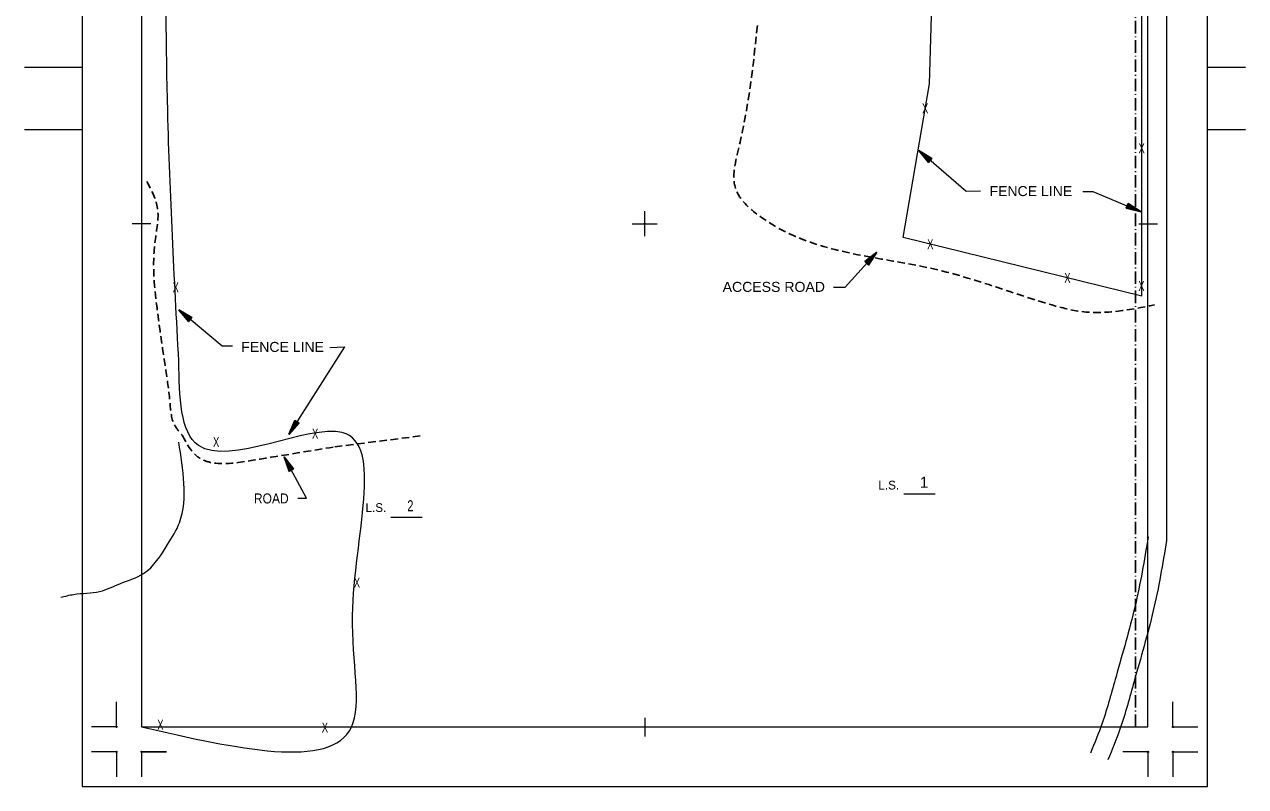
# Model space of a CAD drawing. Extents: x -496 to 480, y -450 to 700.
# Drawn here: x -496 to 480, y -450 to 159 of the extents above; entities that cross this region are included whole.
import ezdxf
from ezdxf.enums import TextEntityAlignment as Align

# ---------------------------------------------------------------- set-up
doc = ezdxf.new("R2010")
doc.units = 0
doc.header["$LTSCALE"] = 2
doc.header["$PDMODE"] = 32
doc.header["$PDSIZE"] = 1
doc.linetypes.add('DOT_DASHED', pattern=[7.7, 5, -1.2, 0.3, -1.2])
doc.linetypes.add('MEDIUM_DASHED', pattern=[4.5, 3, -1.5])
for name, color, linetype, lineweight in [('1', 7, 'Continuous', 13), ('3', 7, 'Continuous', 13), ('4', 7, 'Continuous', 25)]:
    doc.layers.add(name, color=color, linetype=linetype, lineweight=lineweight)

msp = doc.modelspace()

# ---------------------------------------------------------------- linework, layer by layer
at = {"layer": '1'}
for p, q in [((-402.391, 402.339), (-402.391, -402.333)), ((-450.017, 124.973), (-496.057, 124.973)), ((480.331, 124.973), (449.983, 124.973)), ((-450.017, 74.973), (-496.057, 74.973)), ((480.331, 74.973), (449.983, 74.973)), ((-0.017, -10.027), (-0.017, 9.973)), ((-395.017, -0.027), (-410.017, -0.027)), ((-10.017, -0.027), (9.983, -0.027)), ((394.983, -0.027), (409.983, -0.027)), ((207.114, -215.907), (232.114, -215.907)), ((-202.998, -234.618), (-177.998, -234.618)), ((-422.391, -402.333), (-422.391, -382.333)), ((422.281, -402.333), (422.281, -382.333)), ((-0.017, -395.027), (-0.017, -410.027)), ((-422.391, -402.333), (-442.391, -402.333)), ((-402.391, -402.333), (402.281, -402.333)), ((422.281, -402.333), (442.281, -402.333)), ((-422.391, -422.333), (-442.391, -422.333)), ((-422.391, -422.333), (-422.391, -442.333)), ((-402.391, -422.333), (-402.391, -442.333)), ((402.281, -422.333), (382.281, -422.333)), ((402.281, -422.333), (402.281, -442.333)), ((422.281, -422.333), (422.281, -442.333)), ((422.281, -422.333), (442.281, -422.333)), ((-450.017, -450.027), (449.983, -450.027))]:
    msp.add_line(p, q, dxfattribs=at)
for points in [[(449.983, -450.027), (449.983, 399.973), (449.983, 699.973), (-450.017, 699.973), (-450.017, 49.973), (-450.017, -450.027)], [(402.281, -402.333), (402.281, 402.339), (-402.391, 402.339)], [(-402.391, -422.333), (-382.391, -422.333), (-402.391, -422.333)]]:
    msp.add_lwpolyline(points, dxfattribs=at)
for p in [(0, 0), (0.001, -0.011), (-422.391, -402.333), (422.281, -402.333), (-422.391, -422.333), (-402.391, -422.333), (402.281, -422.333), (422.281, -422.333)]:
    msp.add_point(p, dxfattribs=at)
at = {"layer": '3', "linetype": 'DOT_DASHED', "lineweight": 25}
msp.add_line((392.281, -402.333), (392.281, 402.339), dxfattribs=at)
at = {"layer": '3'}
for p, q in [((397.281, -58.045), (397.281, 402.339)), ((417.281, -253.126), (417.281, 402.339))]:
    msp.add_line(p, q, dxfattribs=at)
at = {"layer": '3', "linetype": 'MEDIUM_DASHED', "lineweight": 25}
msp.add_line((-247.932, -178.384), (-179.751, -169.728), dxfattribs=at)
at = {"layer": '3'}
msp.add_lwpolyline([(397.281, -58.045), (206.561, -11.136), (227.531, 111.789), (234.521, 346.464), (234.183, 379.125)], dxfattribs=at)
for points in [[(-372.604, -109.817), (-381.459, 90.018), (-380.682, 399.949)], [(-402.391, -402.333), (-234.544, -402.495), (-233.72, -313.169), (-241.962, -167.035), (-356.944, -177.326), (-372.604, -109.817)], [(-381.561, -256.477), (-372.106, -239.123), (-368.49, -207.828), (-372.708, -174.727)], [(402.465, -250.452), (391.946, -305.905), (376.752, -361.942), (365.648, -399.3), (356.298, -423.233)], [(417.203, -253.247), (406.575, -309.271), (391.182, -366.042), (379.848, -404.175), (370.27, -428.692)], [(-466.977, -298.673), (-456.677, -296.386), (-435.9, -293.991), (-419.119, -287.606), (-400.739, -279.624), (-381.561, -256.477)]]:
    msp.add_spline(points, degree=3, dxfattribs=at)
at = {"layer": '3', "linetype": 'MEDIUM_DASHED', "lineweight": 25}
for points in [[(89.967, 158.387), (75.411, 61.896), (72.764, 27.53), (91.291, 6.381), (235.533, -37.237), (325.518, -64.995), (349.338, -70.282), (407.564, -64.995)], [(-398.18, 33.789), (-389.592, 12.013), (-391.574, -13.723), (-389.592, -71.133), (-382.985, -117.325), (-379.682, -143.06), (-376.379, -160.217), (-370.02, -169.062)], [(-370.02, -169.062), (-354.421, -188.356), (-344.853, -191.264), (-316.151, -189.602), (-247.932, -178.384)]]:
    msp.add_spline(points, degree=3, dxfattribs=at)
at = {"layer": '4', "lineweight": 13}
for points in [[(268.335, 25.94), (256.919, 25.648), (219.159, 58.394)], [(350.294, 25.648), (358.197, 25.648), (396.836, 9.568)], [(150.87, -50.647), (160.144, -50.647), (185.511, -22.857)], [(-329.579, -97.921), (-337.942, -97.921), (-372.684, -69.003)], [(-251.731, -98.884), (-240.151, -98.563), (-284.543, -168.609)], [(-277.538, -219.496), (-270.571, -219.496), (-288.405, -186.374)]]:
    msp.add_lwpolyline(points, dxfattribs=at)
at = {"layer": '4'}
for points in [[(219.159, 58.394), (226.914, 49.021), (229.535, 52.043)], [(396.836, 9.568), (386.525, 16.025), (384.988, 12.332)], [(185.511, -22.857), (175.944, -30.372), (178.898, -33.068)], [(-372.684, -69.003), (-364.741, -78.217), (-362.182, -75.142)], [(-284.543, -168.609), (-276.43, -159.544), (-279.809, -157.403)], [(-288.405, -186.374), (-284.477, -197.888), (-280.955, -195.992)]]:
    msp.add_lwpolyline(points, close=True, dxfattribs=at)
for points in [[(226.918, 49.175), (219.592, 58.017), (229.304, 52.026), (226.998, 49.335), (220.148, 57.535), (229.045, 52.024), (226.968, 49.561), (220.736, 57.025), (228.756, 51.986), (227.011, 49.808), (221.391, 56.43), (228.448, 51.996), (226.989, 50.116), (222.177, 55.717), (228.131, 51.927), (226.996, 50.453), (223.028, 54.952), (227.707, 51.866), (226.955, 50.801), (223.934, 54.08), (227.276, 51.896), (226.88, 51.21), (225.074, 53.119), (226.742, 51.875)], [(386.57, 15.878), (396.306, 9.789), (385.202, 12.421), (386.544, 15.701), (395.626, 10.072), (385.447, 12.504), (386.644, 15.496), (394.908, 10.371), (385.71, 12.631), (386.681, 15.247), (394.099, 10.73), (386.006, 12.719), (386.799, 14.962), (393.128, 11.159), (386.285, 12.883), (386.898, 14.64), (392.08, 11.618), (386.668, 13.075), (387.047, 14.322), (390.946, 12.16), (387.086, 13.182), (387.246, 13.958), (389.561, 12.714), (387.586, 13.37)], [(176.097, -30.379), (185.124, -23.28), (178.887, -32.837), (176.255, -30.464), (184.627, -23.824), (178.891, -32.578), (176.482, -30.439), (184.103, -24.399), (178.861, -32.288), (176.729, -30.488), (183.491, -25.039), (178.879, -31.98), (177.036, -30.474), (182.758, -25.806), (178.818, -31.662), (177.373, -30.49), (181.972, -26.637), (178.768, -31.236), (177.722, -30.457), (181.077, -27.521), (178.809, -30.806), (178.132, -30.393), (180.087, -28.637), (178.801, -30.272)], [(-364.74, -78.063), (-372.244, -69.37), (-362.412, -75.164), (-364.663, -77.901), (-371.678, -69.842), (-362.671, -75.172), (-364.698, -77.676), (-371.079, -70.339), (-362.96, -75.215), (-364.66, -77.428), (-370.413, -70.921), (-363.268, -75.212), (-364.688, -77.121), (-369.612, -71.618), (-363.583, -75.286), (-364.688, -76.784), (-368.746, -72.366), (-364.006, -75.356), (-364.736, -76.436), (-367.823, -73.219), (-364.437, -75.335), (-364.819, -76.029), (-366.663, -74.157), (-364.97, -75.367)], [(-276.582, -159.563), (-284.235, -168.125), (-279.757, -157.628), (-276.753, -159.507), (-283.841, -167.503), (-279.717, -157.884), (-276.971, -159.571), (-283.424, -166.845), (-279.637, -158.165), (-277.223, -159.566), (-282.933, -166.109), (-279.6, -158.471), (-277.523, -159.633), (-282.345, -165.226), (-279.485, -158.774), (-277.858, -159.676), (-281.715, -164.27), (-279.361, -159.184), (-278.196, -159.769), (-280.989, -163.245), (-279.327, -159.614), (-278.589, -159.904), (-280.208, -161.974), (-279.226, -160.139)], [(-284.419, -197.746), (-288.134, -186.88), (-281.177, -195.926), (-284.287, -197.625), (-287.785, -187.529), (-281.42, -195.836), (-284.236, -197.403), (-287.416, -188.214), (-281.704, -195.768), (-284.108, -197.186), (-287.015, -189.002), (-281.989, -195.65), (-284.019, -196.891), (-286.532, -189.948), (-282.309, -195.602), (-283.893, -196.579), (-286.008, -190.965), (-282.727, -195.509), (-283.808, -196.238), (-285.47, -192.101), (-283.119, -195.328), (-283.733, -195.83), (-284.745, -193.405), (-283.626, -195.159)]]:
    msp.add_lwpolyline(points, dxfattribs=at)

# ---------------------------------------------------------------- texts
at = {"layer": '1'}
for s, height, p in [('1', 8.89, (223.338, -211.189)), ('L.S.', 7, (195.033, -212.53)), ('L.S.', 7, (-215.009, -230.48))]:
    msp.add_text(s, height=height, dxfattribs=at).set_placement(p, align=Align.CENTER)
at = {"layer": '1', "width": 0.75}
msp.add_text('2', height=8.89, dxfattribs=at).set_placement((-187.46, -230.008), align=Align.CENTER)
at = {"layer": '3', "width": 0.7}
for p in [(224.171, 88.077), (397.234, 56.242), (228.262, -20.404), (-375.067, -55.001), (337.881, -47.396), (397.059, -53.857), (-263.605, -171.901), (-342.743, -178.581), (-230.166, -291.027), (-387.328, -404.586), (-255.803, -406.813)]:
    msp.add_text('X', height=8, dxfattribs=at).set_placement(p, align=Align.CENTER)
at = {"layer": '4'}
for s, width, p in [('FENCE LINE', 1.05, (308.648, 22.035)), ('ACCESS ROAD', 1.05, (103.12, -54.533)), ('FENCE LINE', 1.05, (-289.593, -102.538)), ('ROAD', 0.9, (-298.68, -223.673))]:
    msp.add_text(s, height=8, dxfattribs=dict(at, width=width)).set_placement(p, align=Align.CENTER)

doc.saveas('drawing.dxf')
